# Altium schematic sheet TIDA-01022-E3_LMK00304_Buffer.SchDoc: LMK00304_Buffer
size 431 x 279 mm; Date: Not shown in title block; ApprovedBy: Not shown in title block; CheckedBy: Not shown in title block; Author: Not shown in title block; CompanyName: Not shown in title block; DrawnBy: Avinash N; Engineer: Not shown in title block; Organization: Not shown in title block; Address1: Not shown in title block; Address2: Not shown in title block; Address3: Not shown in title block; Address4: Not shown in title block; DocumentNumber: 1; Revision: Use project parameter SCH_Rev; SheetNumber: 12; SheetTotal: 26; PageSetup: Record=PageOptions¦CenterHorizontal=True¦CenterVertical=True¦PrintScale=1.00¦XCorrection=1.00¦YCorrection=1.00¦PrintKind=0¦BorderSize=5000000¦LeftOffset=0¦BottomOffset=0¦Orientation=2¦PaperLength=1000¦PaperWidth=1000¦Scale=100¦PaperSource=15¦PrintQuality=600¦MediaType=1¦DitherType=10¦PaperKind=Letter¦PrintScaleMode=1
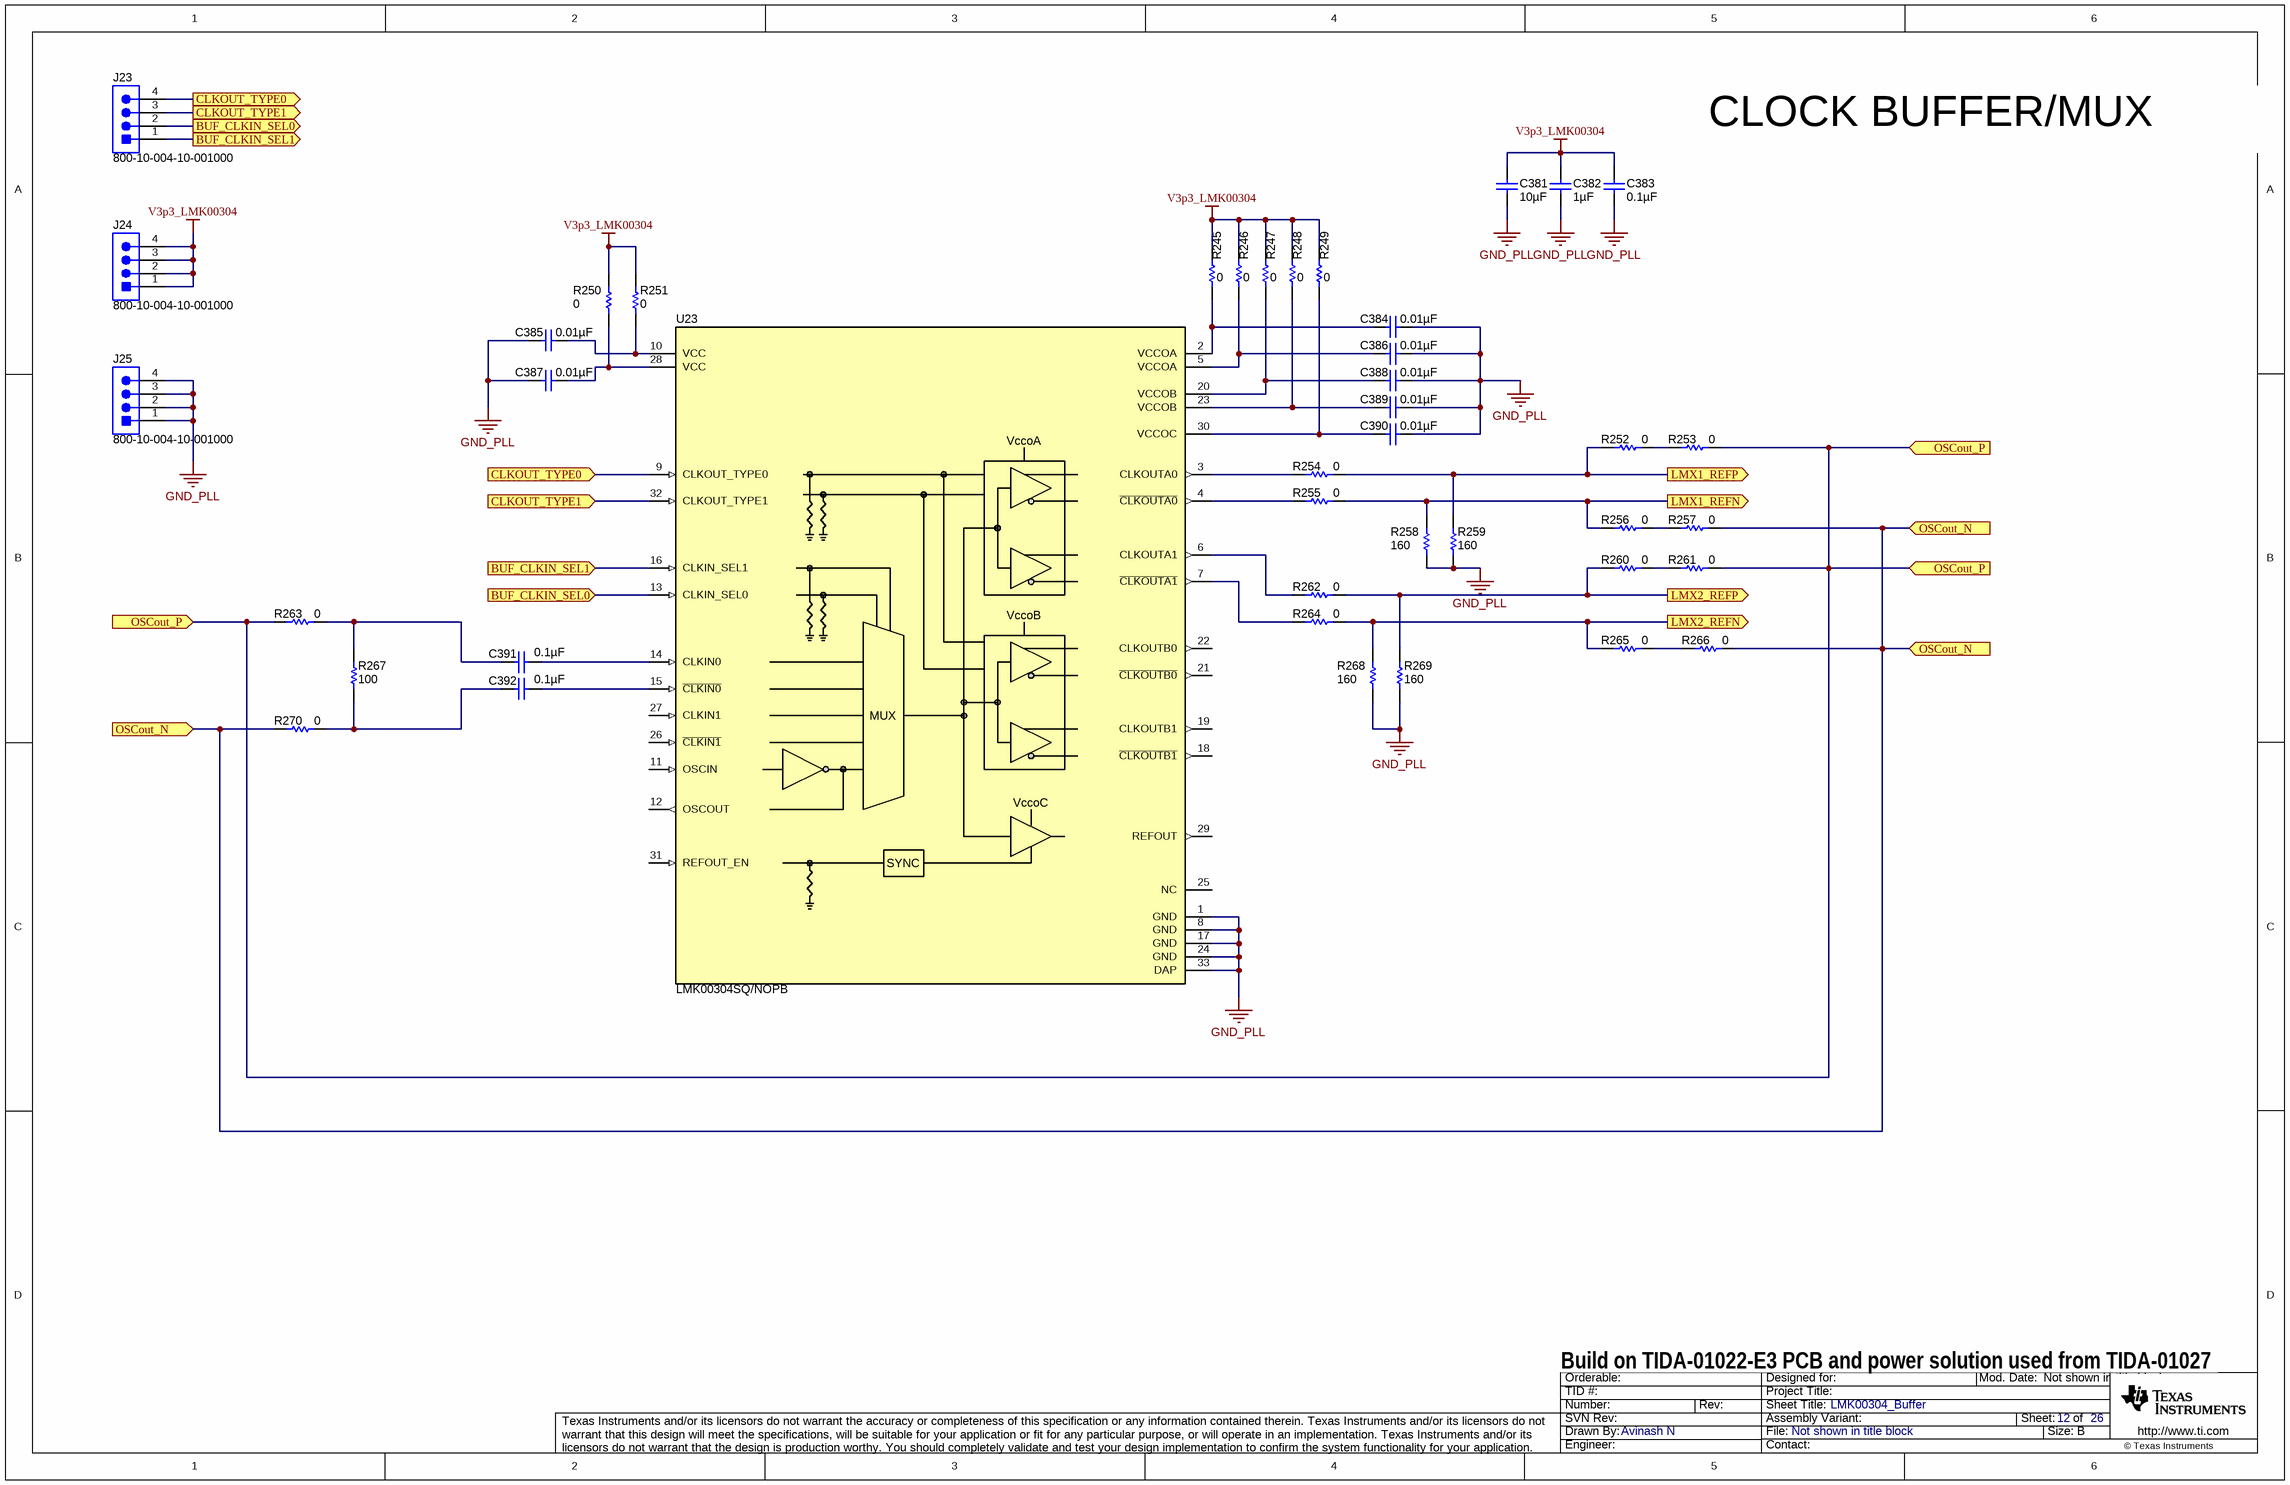
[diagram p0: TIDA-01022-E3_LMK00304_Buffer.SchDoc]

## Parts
C381  ValueDisplayed: 10µF  [0603]  (hidden comment: EMK107BBJ106MA-T)
C382  ValueDisplayed: 1µF  [0402]  (hidden comment: C1005X7S1A105K050BC)
C383  ValueDisplayed: 0.1µF  [0402]  (hidden comment: GRM155R71C104KA88D)
C384  ValueDisplayed: 0.01µF  [0402]  (hidden comment: GRM155R71E103KA01D)
C385  ValueDisplayed: 0.01µF  [0402]  (hidden comment: GRM155R71E103KA01D)
C386  ValueDisplayed: 0.01µF  [0402]  (hidden comment: GRM155R71E103KA01D)
C387  ValueDisplayed: 0.01µF  [0402]  (hidden comment: GRM155R71E103KA01D)
C388  ValueDisplayed: 0.01µF  [0402]  (hidden comment: GRM155R71E103KA01D)
C389  ValueDisplayed: 0.01µF  [0402]  (hidden comment: GRM155R71E103KA01D)
C390  ValueDisplayed: 0.01µF  [0402]  (hidden comment: GRM155R71E103KA01D)
C391  ValueDisplayed: 0.1µF  [0402]  (hidden comment: C1005X7R1E104M050BB)
C392  ValueDisplayed: 0.1µF  [0402]  (hidden comment: C1005X7R1E104M050BB)
J23  800-10-004-10-001000  [Mill-Max_800-10-004-10-001000]
J24  800-10-004-10-001000  [Mill-Max_800-10-004-10-001000]
J25  800-10-004-10-001000  [Mill-Max_800-10-004-10-001000]
R245  ValueDisplayed: 0  [0402]  (hidden comment: CRCW04020000Z0ED)
R246  ValueDisplayed: 0  [0402]  (hidden comment: CRCW04020000Z0ED)
R247  ValueDisplayed: 0  [0402]  (hidden comment: CRCW04020000Z0ED)
R248  ValueDisplayed: 0  [0402]  (hidden comment: CRCW04020000Z0ED)
R249  ValueDisplayed: 0  [0402]  (hidden comment: CRCW04020000Z0ED)
R250  ValueDisplayed: 0  [0402]  (hidden comment: CRCW04020000Z0ED)
R251  ValueDisplayed: 0  [0402]  (hidden comment: CRCW04020000Z0ED)
R252  ValueDisplayed: 0  [0402]  (hidden comment: CRCW04020000Z0ED)
R253  ValueDisplayed: 0  [0402]  (hidden comment: CRCW04020000Z0ED)
R254  ValueDisplayed: 0  [0402]  (hidden comment: CRCW04020000Z0ED)
R255  ValueDisplayed: 0  [0402]  (hidden comment: CRCW04020000Z0ED)
R256  ValueDisplayed: 0  [0402]  (hidden comment: CRCW04020000Z0ED)
R257  ValueDisplayed: 0  [0402]  (hidden comment: CRCW04020000Z0ED)
R258  ValueDisplayed: 160  [0402]  (hidden comment: CRCW0402160RJNED)
R259  ValueDisplayed: 160  [0402]  (hidden comment: CRCW0402160RJNED)
R260  ValueDisplayed: 0  [0402]  (hidden comment: CRCW04020000Z0ED)
R261  ValueDisplayed: 0  [0402]  (hidden comment: CRCW04020000Z0ED)
R262  ValueDisplayed: 0  [0402]  (hidden comment: CRCW04020000Z0ED)
R263  ValueDisplayed: 0  [0402]  (hidden comment: CRCW04020000Z0ED)
R264  ValueDisplayed: 0  [0402]  (hidden comment: CRCW04020000Z0ED)
R265  ValueDisplayed: 0  [0402]  (hidden comment: CRCW04020000Z0ED)
R266  ValueDisplayed: 0  [0402]  (hidden comment: CRCW04020000Z0ED)
R267  ValueDisplayed: 100  [0402]  (hidden comment: CRCW0402100RFKED)
R268  ValueDisplayed: 160  [0402]  (hidden comment: CRCW0402160RJNED)
R269  ValueDisplayed: 160  [0402]  (hidden comment: CRCW0402160RJNED)
R270  ValueDisplayed: 0  [0402]  (hidden comment: CRCW04020000Z0ED)
U23  LMK00304SQ/NOPB  [RTV0032A]

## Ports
BUF_CLKIN_SEL0 (in), BUF_CLKIN_SEL0 (out), BUF_CLKIN_SEL1 (in), BUF_CLKIN_SEL1 (out), CLKOUT_TYPE0 (in), CLKOUT_TYPE0 (out), CLKOUT_TYPE1 (in), CLKOUT_TYPE1 (out), LMX1_REFN (out), LMX1_REFP (out), LMX2_REFN (out), LMX2_REFP (out), OSCout_N (in), OSCout_P (in)

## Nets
GND_PLL: C381.2 C382.2 C383.2 C384.2 C385.1 C386.2 C387.1 C388.2 C389.2 C390.2 J25.1 J25.2 J25.3 J25.4 R258.1 R259.1 R268.1 R269.1 U23.1(GND) U23.8(GND) U23.17(GND) U23.24(GND) U23.33(DAP)
V3p3_LMK00304: C381.1 C382.1 C383.1 J24.1 J24.2 J24.3 J24.4 R245.2 R246.2 R247.2 R248.2 R249.2 R250.2 R251.2
BUF_CLKIN_SEL0: J23.2 U23.13(CLKIN_SEL0) ; port BUF_CLKIN_SEL0
BUF_CLKIN_SEL1: J23.1 U23.16(CLKIN_SEL1) ; port BUF_CLKIN_SEL1
CLKOUT_TYPE0: J23.4 U23.9(CLKOUT_TYPE0) ; port CLKOUT_TYPE0
CLKOUT_TYPE1: J23.3 U23.32(CLKOUT_TYPE1) ; port CLKOUT_TYPE1
LMX1_REFN: R255.2 R256.1 R258.2 ; port LMX1_REFN
LMX1_REFP: R252.1 R254.2 R259.2 ; port LMX1_REFP
LMX2_REFN: R264.2 R265.1 R268.2 ; port LMX2_REFN
LMX2_REFP: R260.1 R262.2 R269.2 ; port LMX2_REFP
OSCout_N: R257.2 R266.2 R270.1 ; port OSCout_N
OSCout_P: R253.2 R261.2 R263.1 ; port OSCout_P
NetC384_1: C384.1 R245.1 U23.2(VCCOA)
NetC385_2: C385.2 R251.1 U23.10(VCC)
NetC386_1: C386.1 R246.1 U23.5(VCCOA)
NetC387_2: C387.2 R250.1 U23.28(VCC)
NetC388_1: C388.1 R247.1 U23.20(VCCOB)
NetC389_1: C389.1 R248.1 U23.23(VCCOB)
NetC390_1: C390.1 R249.1 U23.30(VCCOC)
NetC391_1: C391.1 R263.2 R267.2
NetC391_2: C391.2 U23.14(CLKIN0)
NetC392_1: C392.1 R267.1 R270.2
NetC392_2: C392.2 U23.15(~{CLKIN0})
NetR252_2: R252.2 R253.1
NetR254_1: R254.1 U23.3(CLKOUTA0)
NetR255_1: R255.1 U23.4(~{CLKOUTA0})
NetR256_2: R256.2 R257.1
NetR260_2: R260.2 R261.1
NetR262_1: R262.1 U23.6(CLKOUTA1)
NetR264_1: R264.1 U23.7(~{CLKOUTA1})
NetR265_2: R265.2 R266.1

Not connected (* = marked no-connect by the designer): U23 11(OSCIN) 12(OSCOUT) 18(~{CLKOUTB1}) 19(CLKOUTB1) 21(~{CLKOUTB0}) 22(CLKOUTB0) 25(NC) 26(~{CLKIN1}) 27(CLKIN1) 29(REFOUT) 31(REFOUT_EN)

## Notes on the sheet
- CLOCK BUFFER/MUX
- Build on TIDA-01022-E3 PCB and power solution used from TIDA-01027

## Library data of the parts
C381 = EMK107BBJ106MA-T: CAP, CERM, 10 µF, 16 V, +/- 20%, X5R, 0603; Manufacturer: Taiyo Yuden; Polarized: N; CompType: Capacitor; Value: 10uF; U/M: EA; Cap_F: 0.00001; Tolerance_%: 20; Value1: Unknown; VDC_V: 16; Value2: 16V; TaMin_C: -55; TaMax_C: 85; SizeArea_mm2: 1.28; SizeAreaWB_mm2: 4.68; SizeX_mm: 1.6; SizeY_mm: 0.8; SizeZ_mm: 1; AEC Category: Q200
C382 = C1005X7S1A105K050BC: CAP, CERM, 1 µF, 10 V, +/- 10%, X7S, 0402; Manufacturer: TDK; Polarized: N; CompType: Capacitor; Value: 1uF; U/M: EA; Cap_F: 0.000001; Tolerance_%: 10; ESR_ohm: 0.011416; Value1: 0.011416 ohm; Value2: 10V; IRMS_A: 1.483; TaMin_C: -55; TaMax_C: 125; SizeArea_mm2: 0.5; SizeAreaWB_mm2: 3; SizeX_mm: 1; SizeZ_mm: 0.6; AEC Category: Q200
C383 = GRM155R71C104KA88D: CAP, CERM, 0.1 µF, 16 V, +/- 10%, X7R, 0402; Manufacturer: MuRata; Polarized: N; CompType: Capacitor; Value: 0.1uF; U/M: EA; Cap_F: 0.0000001; Tolerance_%: 10; Value1: Unknown; VDC_V: 16; Value2: 16V; TaMin_C: -55; TaMax_C: 125; SizeArea_mm2: 0.5; SizeAreaWB_mm2: 3; SizeX_mm: 1; SizeZ_mm: 0.6; AEC Category: Q200
C384-C390 = GRM155R71E103KA01D: CAP, CERM, 0.01 µF, 25 V, +/- 10%, X7R, 0402; Manufacturer: MuRata; Polarized: N; CompType: Capacitor; Value: 0.01uF; U/M: EA; Cap_F: 0.00000001; Tolerance_%: 10; Value1: Unknown; VDC_V: 25; Value2: 25V; TaMin_C: -55; TaMax_C: 125; SizeArea_mm2: 0.5; SizeAreaWB_mm2: 3; SizeX_mm: 1; SizeZ_mm: 0.6; AEC Category: Q200
C391 C392 = C1005X7R1E104M050BB: CAP, CERM, 0.1 µF, 25 V, +/- 20%, X7R, 0402; Manufacturer: TDK; Polarized: N; TaMax_C: 125; TaMin_C: -55; Tolerance_%: 20; VDC_V: 25; Cap_F: 0.0000001; CompType: Capacitor; Value: 0.1uF; Value1: Unknown; Value2: 25V; U/M: EA; SizeArea_mm2: 0.5; SizeAreaWB_mm2: 3; SizeX_mm: 1; SizeZ_mm: 0.6; AEC Category: Q200
J23-J25 = 800-10-004-10-001000: Header, 100mil, 4x1, TH; Manufacturer: Mill-Max; SymbolCreator: a0412235
R245-R257 R260-R266 R270 = CRCW04020000Z0ED: RES, 0, 5%, 0.063 W, 0402; Manufacturer: Vishay-Dale; CompType: Resistor; Value: 0; Value_Code: 0000; Tolerance_%: 5; Power_W: 0.063; Value2: 0.063W; VDC_V: 50; TempCo: 200 ppm/C; SizeArea_mm2: 0.5; SizeX_mm: 1; SizeZ_mm: 0.6; EIA_Code: E24; U/M: EA; AEC Category: Q200
R258 R259 R268 R269 = CRCW0402160RJNED: RES, 160, 5%, 0.063 W, 0402; Manufacturer: Vishay-Dale; CompType: Resistor; Value: 160; Value_Code: 160R; Tolerance_%: 5; Power_W: 0.063; Value2: 0.063W; VDC_V: 50; TempCo: 200 ppm/C; SizeArea_mm2: 0.5; SizeX_mm: 1; SizeZ_mm: 0.6; EIA_Code: E24; U/M: EA; AEC Category: Q200
R267 = CRCW0402100RFKED: RES, 100, 1%, 0.063 W, 0402; Manufacturer: Vishay-Dale; CompType: Resistor; Value: 100; Value_Code: 100R; Tolerance_%: 1; Power_W: 0.063; Value2: 0.063W; VDC_V: 50; TempCo: 100 ppm/C; SizeArea_mm2: 0.5; SizeZ_mm: 0.6; EIA_Code: E96; U/M: EA; AEC Category: Q200
U23 = LMK00304SQ/NOPB: 3.1-GHz Differential Clock Buffer/Level Translator, RTV0032A (WQFN-32); Manufacturer: Texas Instruments; SymbolCreator: a0411947; SizeArea_mm2: 25; SizeAreaWB_mm2: 49; SizeX_mm: 5; SizeZ_mm: 0.8; CompType: IC; U/M: EA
